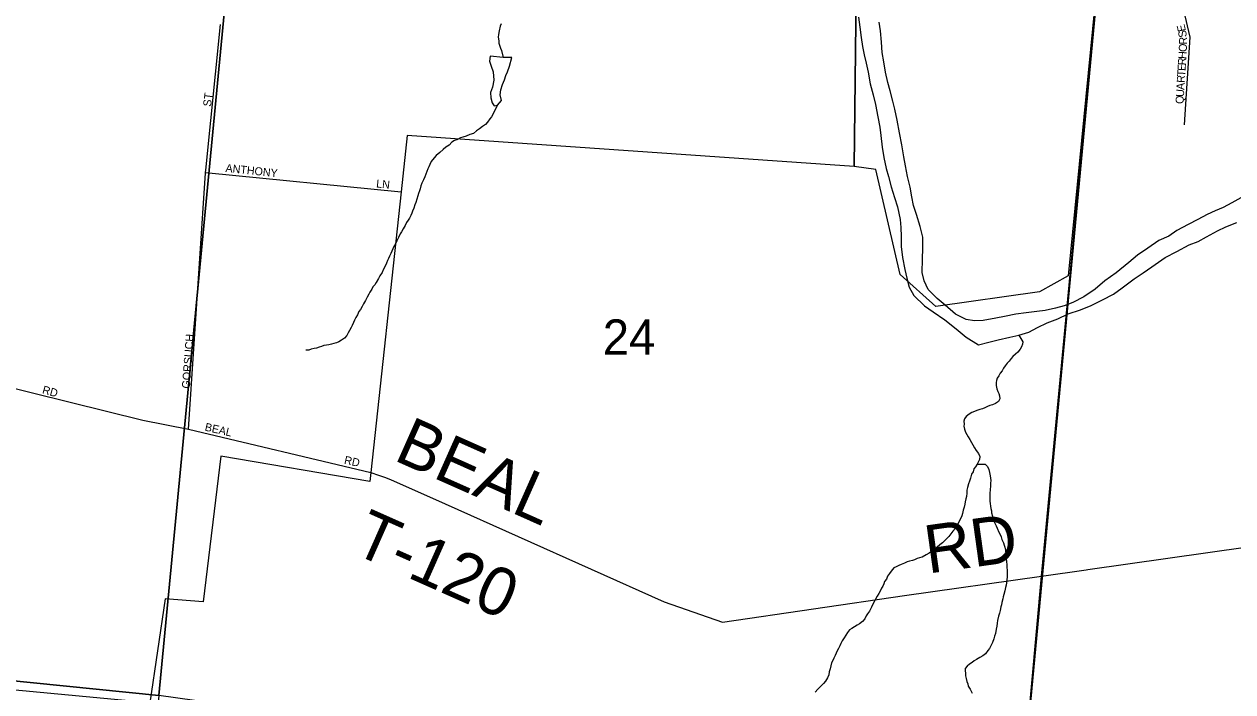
# Model space of a CAD drawing. Extents: x 0 to 1064, y 0 to 440.
# Drawn here: x 184.46 to 207.35, y 344.95 to 357.59 of the extents above; entities that cross this region are included whole.
import ezdxf

# ---------------------------------------------------------------- set-up
doc = ezdxf.new("R2010")
doc.units = 0
for name, color, linetype in [('GM_X_City_Street', 7, 'Continuous'), ('GM_X_City_Street_Text', 7, 'Continuous'), ('GM_X_Corporation', 7, 'Continuous'), ('GM_X_Minor_River', 7, 'Continuous'), ('GM_X_Section', 7, 'Continuous'), ('GM_X_Section_Text', 7, 'Continuous'), ('GM_X_Township', 7, 'Continuous'), ('GM_X_Township_Road', 7, 'Continuous'), ('GM_X_Township_Road_Text', 7, 'Continuous'), ('GM_X_Township_Subdivision', 7, 'Continuous'), ('GM_X_Township_Subdivision_Text', 7, 'Continuous')]:
    doc.layers.add(name, color=color, linetype=linetype)

msp = doc.modelspace()

# ---------------------------------------------------------------- linework, layer by layer
at = {"layer": 'GM_X_City_Street'}
for points in [[(187.899, 354.826), (188.175, 357.579)], [(187.57, 349.918), (187.893, 354.768), (187.894, 354.779), (187.899, 354.826)], [(187.894, 354.779), (191.598, 354.412)], [(176.764, 352.216), (177.99, 352.1), (178.74, 352.032), (178.977, 352.01), (179.136, 352.067), (179.239, 352.151), (179.329, 352.284), (179.415, 352.448), (179.642, 352.416), (180.906, 352.048), (181.392, 351.894), (181.99, 351.683), (182.33, 351.543), (183.604, 350.877), (183.923, 350.781), (186.704, 350.093), (187.57, 349.918)], [(187.57, 349.918), (191.021, 349.103), (191.167, 349.051), (191.281, 349.01)]]:
    msp.add_lwpolyline(points, dxfattribs=at)
at = {"layer": 'GM_X_Corporation'}
for points in [[(205.238, 363.077), (204.231, 352.82), (203.687, 352.519), (201.723, 352.242), (201.048, 352.85), (200.589, 354.837), (200.178, 354.895), (200.225, 359.253)], [(200.225, 359.253), (200.178, 354.895), (191.714, 355.477), (191.598, 354.412), (191.021, 349.103), (191.003, 348.93), (188.184, 349.411), (187.85, 346.651), (187.13, 346.708), (186.837, 344.742), (178.526, 345.524)]]:
    msp.add_lwpolyline(points, dxfattribs=at)
at = {"layer": 'GM_X_Minor_River'}
for points in [[(193.49, 357.594), (193.471, 357.546), (193.451, 357.461), (193.443, 357.394), (193.436, 357.34), (193.447, 357.273), (193.446, 357.23), (193.457, 357.187), (193.48, 357.132), (193.497, 357.089), (193.531, 356.955)], [(200.26, 357.72), (200.285, 357.531), (200.31, 357.336), (200.336, 357.165), (200.368, 357.006), (200.401, 356.847), (200.439, 356.676), (200.481, 356.456), (200.537, 356.249), (200.58, 356.065), (200.623, 355.833), (200.66, 355.638), (200.68, 355.479), (200.705, 355.26), (200.736, 355.065), (200.78, 354.857), (200.824, 354.704), (200.88, 354.508), (200.941, 354.306), (200.997, 354.129), (201.046, 353.891), (201.06, 353.738), (201.067, 353.568), (201.069, 353.38), (201.093, 353.167), (201.136, 352.941), (201.174, 352.782), (201.218, 352.611), (201.305, 352.45), (201.506, 352.257), (201.673, 352.143), (201.894, 351.992), (202.108, 351.823), (202.298, 351.66), (202.531, 351.52), (202.726, 351.57), (202.903, 351.614), (203.123, 351.663), (203.294, 351.702), (203.483, 351.758), (203.65, 351.845), (203.834, 351.931), (204.036, 352.011), (204.227, 352.103), (204.465, 352.182), (204.662, 352.263), (204.877, 352.367), (205.086, 352.477), (205.253, 352.594), (205.482, 352.764), (205.648, 352.882), (205.815, 352.993), (206.069, 353.169), (206.29, 353.285), (206.518, 353.407), (206.689, 353.475), (206.849, 353.562), (207.059, 353.678), (207.218, 353.753), (207.421, 353.833)], [(201.474, 353.552), (201.424, 353.754), (201.357, 353.986), (201.301, 354.152), (201.269, 354.316), (201.237, 354.499), (201.188, 354.701), (201.151, 354.903), (201.119, 355.073), (201.082, 355.305), (201.034, 355.531), (200.991, 355.769), (200.948, 355.977), (200.91, 356.13), (200.86, 356.325), (200.816, 356.485), (200.772, 356.68), (200.741, 356.875), (200.709, 357.052), (200.696, 357.247), (200.678, 357.46), (200.652, 357.625)], [(193.531, 356.955), (193.281, 356.984), (193.273, 356.887), (193.301, 356.795), (193.34, 356.685), (193.354, 356.527), (193.327, 356.394), (193.287, 356.292), (193.297, 356.194), (193.319, 356.096), (193.36, 356.041), (193.421, 356.051), (193.496, 356.141), (193.474, 356.25), (193.483, 356.347), (193.516, 356.444), (193.555, 356.534)], [(193.555, 356.534), (193.581, 356.618), (193.613, 356.684), (193.652, 356.793), (193.693, 356.956), (193.531, 356.955)], [(193.421, 356.051), (193.306, 355.835), (193.275, 355.793), (193.231, 355.733), (193.194, 355.685), (193.138, 355.65), (193.083, 355.603), (193.027, 355.567), (192.966, 355.52), (192.898, 355.497), (192.831, 355.468), (192.764, 355.446), (192.721, 355.434), (192.653, 355.399), (192.611, 355.382), (192.555, 355.353), (192.506, 355.299), (192.444, 355.258), (192.395, 355.216), (192.327, 355.157), (192.259, 355.104), (192.221, 355.056), (192.165, 354.99), (192.14, 354.93), (192.12, 354.888), (192.101, 354.846), (192.082, 354.798), (192.049, 354.695), (192.018, 354.641), (191.992, 354.575), (191.973, 354.526), (191.96, 354.472), (191.947, 354.43), (191.927, 354.382), (191.914, 354.339), (191.895, 354.273), (191.875, 354.213), (191.856, 354.164), (191.836, 354.104), (191.811, 354.05), (191.798, 354.008), (191.779, 353.965), (191.753, 353.917), (191.728, 353.875), (191.697, 353.833), (191.671, 353.779), (191.634, 353.713), (191.602, 353.659), (191.577, 353.617), (191.545, 353.551), (191.513, 353.485), (191.488, 353.431), (191.462, 353.376), (191.437, 353.334), (191.405, 353.244), (191.374, 353.196), (191.36, 353.154), (191.341, 353.112), (191.322, 353.063), (191.297, 353.003), (191.259, 352.937), (191.239, 352.889), (191.196, 352.823), (191.17, 352.775), (191.126, 352.697), (191.101, 352.655), (191.063, 352.613), (191.044, 352.571), (191.007, 352.517), (190.988, 352.475), (190.956, 352.421), (190.924, 352.355), (190.887, 352.295), (190.861, 352.241), (190.83, 352.187), (190.798, 352.145), (190.773, 352.084), (190.741, 352.037), (190.716, 351.982), (190.697, 351.94), (190.671, 351.886), (190.652, 351.844), (190.621, 351.79), (190.595, 351.742), (190.57, 351.694), (190.527, 351.646), (190.471, 351.605), (190.416, 351.576), (190.373, 351.552), (190.324, 351.541), (190.281, 351.53), (190.226, 351.519), (190.184, 351.508), (190.135, 351.503), (190.092, 351.485), (190.043, 351.474), (189.995, 351.457), (189.952, 351.446), (189.891, 351.435), (189.848, 351.418), (189.793, 351.413)], [(207.555, 354.328), (207.327, 354.206), (207.167, 354.119), (207.014, 354.056), (206.86, 353.981), (206.682, 353.888), (206.504, 353.796), (206.288, 353.68), (206.134, 353.574), (205.944, 353.494), (205.74, 353.347), (205.542, 353.212), (205.381, 353.077), (205.139, 352.882), (204.923, 352.73), (204.742, 352.57), (204.526, 352.424), (204.317, 352.32), (204.152, 352.257), (203.987, 352.213), (203.791, 352.169), (203.633, 352.149), (203.432, 352.123), (203.238, 352.098), (203.024, 352.055), (202.859, 352.022), (202.622, 351.98), (202.458, 351.972), (202.3, 351.994), (202.097, 352.096), (201.901, 352.265), (201.747, 352.391), (201.581, 352.565), (201.501, 352.731), (201.462, 352.884), (201.469, 353.139), (201.474, 353.345), (201.474, 353.552)], [(203.294, 351.702), (203.372, 351.574), (203.365, 351.532), (203.346, 351.477), (203.321, 351.435), (203.277, 351.381), (203.234, 351.34), (203.184, 351.298), (203.147, 351.257), (203.109, 351.209), (203.072, 351.167), (203.035, 351.119), (203.003, 351.077), (202.978, 351.023), (202.941, 350.981), (202.915, 350.933), (202.884, 350.885), (202.871, 350.843), (202.864, 350.801), (202.869, 350.746), (202.88, 350.685), (202.897, 350.636), (202.914, 350.593), (202.931, 350.55), (202.936, 350.495), (202.911, 350.447), (202.855, 350.406), (202.794, 350.383), (202.745, 350.366), (202.702, 350.348), (202.653, 350.325), (202.604, 350.308), (202.555, 350.291), (202.5, 350.274), (202.458, 350.256), (202.403, 350.233), (202.353, 350.204), (202.298, 350.163), (202.266, 350.115), (202.253, 350.072), (202.258, 350.018), (202.251, 349.975), (202.268, 349.92), (202.285, 349.865), (202.309, 349.822), (202.338, 349.773), (202.367, 349.723), (202.396, 349.668), (202.426, 349.625), (202.455, 349.57), (202.49, 349.514), (202.531, 349.458), (202.554, 349.403), (202.553, 349.349), (202.534, 349.306), (202.509, 349.258), (202.477, 349.21), (202.446, 349.169), (202.433, 349.114), (202.401, 349.066), (202.382, 348.994), (202.362, 348.939), (202.343, 348.885), (202.323, 348.819), (202.31, 348.764), (202.309, 348.71), (202.301, 348.649), (202.294, 348.6), (202.281, 348.546), (202.274, 348.498), (202.26, 348.443), (202.241, 348.389), (202.227, 348.322), (202.214, 348.28), (202.195, 348.238), (202.164, 348.178), (202.132, 348.112), (202.094, 348.046), (202.044, 347.992), (202.007, 347.938), (201.969, 347.89), (201.932, 347.848), (201.851, 347.771), (201.796, 347.73), (201.746, 347.688), (201.703, 347.647), (201.641, 347.606), (201.598, 347.576), (201.543, 347.541), (201.463, 347.5), (201.414, 347.483), (201.371, 347.472), (201.322, 347.448), (201.28, 347.437), (201.225, 347.42), (201.182, 347.409), (201.127, 347.386), (201.065, 347.357)], [(202.509, 349.258), (202.66, 349.261), (202.702, 349.212), (202.725, 349.156), (202.742, 349.101), (202.753, 349.04), (202.758, 348.992), (202.763, 348.949), (202.756, 348.9), (202.761, 348.84), (202.753, 348.779), (202.745, 348.706), (202.744, 348.651), (202.749, 348.609), (202.748, 348.56), (202.753, 348.511), (202.758, 348.463), (202.764, 348.42), (202.775, 348.377), (202.78, 348.335), (202.797, 348.273), (202.814, 348.224), (202.831, 348.169), (202.866, 348.09), (202.883, 348.047), (202.918, 347.973), (202.941, 347.924), (202.958, 347.881), (202.975, 347.832), (203.004, 347.771), (203.015, 347.728), (203.027, 347.685), (203.044, 347.63), (203.048, 347.563), (203.059, 347.508), (203.058, 347.459), (203.063, 347.417), (203.068, 347.35), (203.067, 347.301), (203.072, 347.252), (203.076, 347.173), (203.075, 347.131), (203.068, 347.064), (203.061, 347.009), (203.054, 346.967), (203.04, 346.925), (203.027, 346.858), (203.013, 346.792), (203, 346.749), (202.993, 346.707), (202.974, 346.641), (202.967, 346.598), (202.954, 346.556), (202.94, 346.489), (202.927, 346.435), (202.913, 346.38), (202.893, 346.296), (202.886, 346.247), (202.879, 346.193), (202.865, 346.132), (202.852, 346.054), (202.832, 346.005), (202.819, 345.951), (202.799, 345.885), (202.774, 345.83), (202.742, 345.77), (202.711, 345.728), (202.667, 345.669), (202.612, 345.633), (202.556, 345.598), (202.495, 345.563), (202.452, 345.533), (202.409, 345.504), (202.36, 345.475), (202.316, 345.433), (202.279, 345.391), (202.278, 345.343), (202.283, 345.3), (202.288, 345.251), (202.299, 345.202), (202.31, 345.147), (202.327, 345.098), (202.338, 345.056), (202.373, 345), (202.414, 344.926)], [(201.065, 347.357), (201.023, 347.339), (200.973, 347.316), (200.931, 347.293), (200.875, 347.233), (200.843, 347.191), (200.806, 347.137), (200.786, 347.083), (200.749, 347.035), (200.736, 346.993), (200.717, 346.951), (200.692, 346.909), (200.672, 346.855), (200.641, 346.807), (200.615, 346.759), (200.572, 346.693), (200.534, 346.621), (200.502, 346.554), (200.464, 346.476), (200.432, 346.428), (200.407, 346.386), (200.376, 346.332), (200.332, 346.278), (200.276, 346.237), (200.233, 346.208), (200.184, 346.178), (200.135, 346.149), (200.086, 346.12), (200.048, 346.072), (200.017, 346.024), (199.985, 345.97), (199.948, 345.916), (199.922, 345.862), (199.903, 345.82), (199.878, 345.772), (199.853, 345.724), (199.839, 345.681), (199.82, 345.639), (199.789, 345.585), (199.77, 345.543), (199.75, 345.495), (199.737, 345.44), (199.724, 345.386), (199.704, 345.326), (199.697, 345.271), (199.671, 345.211), (199.634, 345.151), (199.596, 345.109), (199.547, 345.055), (199.491, 345.002), (199.441, 344.942)]]:
    msp.add_lwpolyline(points, dxfattribs=at)
at = {"layer": 'GM_X_Section'}
for points in [[(188.579, 361.283), (187.008, 344.881), (170.322, 346.561), (171.779, 362.681)], [(204.837, 358.818), (203.317, 342.596), (187.008, 344.881), (188.579, 361.283)], [(222.155, 361.074), (220.661, 344.384), (203.317, 342.596), (204.837, 358.818)], [(170.322, 346.561), (187.008, 344.881), (185.631, 328.553), (168.83, 330.174)]]:
    msp.add_lwpolyline(points, close=True, dxfattribs=at)
at = {"layer": 'GM_X_Township'}
for points in [[(202.693, 335.755), (203.722, 347.141), (205.238, 363.077), (205.255, 363.253), (205.262, 363.458), (205.364, 364.533), (206.065, 371.769)], [(206.065, 371.769), (205.364, 364.533), (205.262, 363.458), (205.255, 363.253), (205.238, 363.077), (203.722, 347.141), (202.693, 335.755)]]:
    msp.add_lwpolyline(points, dxfattribs=at)
at = {"layer": 'GM_X_Township_Road'}
for points in [[(191.281, 349.01), (191.394, 348.97), (192.434, 348.509), (196.579, 346.652), (197.681, 346.269), (201.129, 346.774), (203.722, 347.141), (204.57, 347.261), (204.603, 347.265)], [(204.603, 347.265), (208.391, 347.801), (208.667, 347.912), (208.587, 346.691), (208.602, 346.563), (208.696, 346.415)]]:
    msp.add_lwpolyline(points, dxfattribs=at)
at = {"layer": 'GM_X_Township_Subdivision'}
msp.add_lwpolyline([(206.434, 355.68), (206.543, 357.338), (206.423, 357.854), (206.532, 359.733), (206.62, 360.611), (206.478, 361.369), (206.337, 362.209), (206.378, 362.376), (206.466, 362.566), (206.752, 362.907), (206.796, 363.071), (206.785, 363.555)], dxfattribs=at)

# ---------------------------------------------------------------- texts
at = {"layer": 'GM_X_City_Street_Text'}
for s, rotation, p in [('ST', 82.8783, (187.995, 356.02)), ('ANTHONY', 354.1259, (188.266, 354.791)), ('LN', 353.9946, (191.119, 354.498)), ('GORSUCH', 85.6702, (187.595, 350.685)), ('RD', 344.4596, (184.79, 350.602)), ('BEAL', 347.1199, (187.869, 349.895)), ('RD', 347.4763, (190.509, 349.269))]:
    msp.add_text(s, height=0.1515, rotation=rotation, dxfattribs=at).set_placement(p)
at = {"layer": 'GM_X_Section_Text'}
msp.add_text('24', height=0.6697, rotation=0, dxfattribs=at).set_placement((195.416, 351.329))
at = {"layer": 'GM_X_Township_Road_Text'}
for s, rotation, p in [('BEAL', 336.0133, (191.434, 349.344)), ('T-120', 336.0668, (190.64, 347.592)), ('RD', 7.924, (201.575, 347.186))]:
    msp.add_text(s, height=0.9091, rotation=rotation, dxfattribs=at).set_placement(p)
at = {"layer": 'GM_X_Township_Subdivision_Text'}
for s, rotation, p in [('E', 102.5437, (206.461, 357.462)), ('S', 99.6819, (206.48, 357.348)), ('R', 89.3763, (206.481, 357.199)), ('O', 86.4573, (206.473, 357.057)), ('R', 86.4509, (206.457, 356.805)), ('H', 86.4573, (206.465, 356.924)), ('T', 86.4428, (206.444, 356.592)), ('E', 86.4818, (206.451, 356.698)), ('A', 86.4573, (206.428, 356.339)), ('R', 86.4505, (206.437, 356.472)), ('Q', 86.4564, (206.412, 356.073)), ('U', 86.4573, (206.42, 356.206))]:
    msp.add_text(s, height=0.152, rotation=rotation, dxfattribs=at).set_placement(p)

doc.saveas('drawing.dxf')
